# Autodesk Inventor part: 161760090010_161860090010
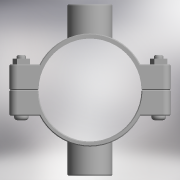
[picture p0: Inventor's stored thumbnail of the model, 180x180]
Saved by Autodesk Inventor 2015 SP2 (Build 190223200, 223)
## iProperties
Created: 2017-05
Part Number: 161760090010_161860090010
Material: Generic
Description: PLASSON DOUBLE SADDLE 90-1"
Document SubType Name: Modeling
Designer: KIM
Density: 1 g/cm^3
Appearance: Default
Author: KIM
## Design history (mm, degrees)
derived "16176.ipt"
feature "Solid1::16176.ipt"
feature "Solid2::16176.ipt"
tag "TaggingFeature1"
body "Solid1"
body "Solid2"
other parameters: "d0" = 99, "d1" = 141, "d2" = 45, "d4" = 105, "d5" = 0, "d6" = 7.05, "d7" = 141, "d8" = 0.1, "d10" = 0, "d11" = 0.9, "d20" = 0.9, "d23" = 0.9, "d36" = 13, "d37" = 10.4, "d38" = 53, "d39" = 0, "d40" = 3, "d41" = 5, "d42" = 0, "d43" = 8, "d44" = 3, "d45" = 0, "d46" = 0.9, "d52" = 30.291, "d53" = 21, "d54" = 0, "d55" = 25, "d57" = 0, "d58" = 97.2, "d60" = 0, "d62" = 13, "d63" = 10.4, "d66" = 84.2, "d68" = 39.3783, "d69" = 30.291, "d70" = 21, "d71" = 0, "d72" = 25, "d74" = 0, "d75" = 0.9, "B_" = 25, "G_" = 30.291, "A_" = 75, "L_" = 141, "L_1" = 105, "l_2" = 21
